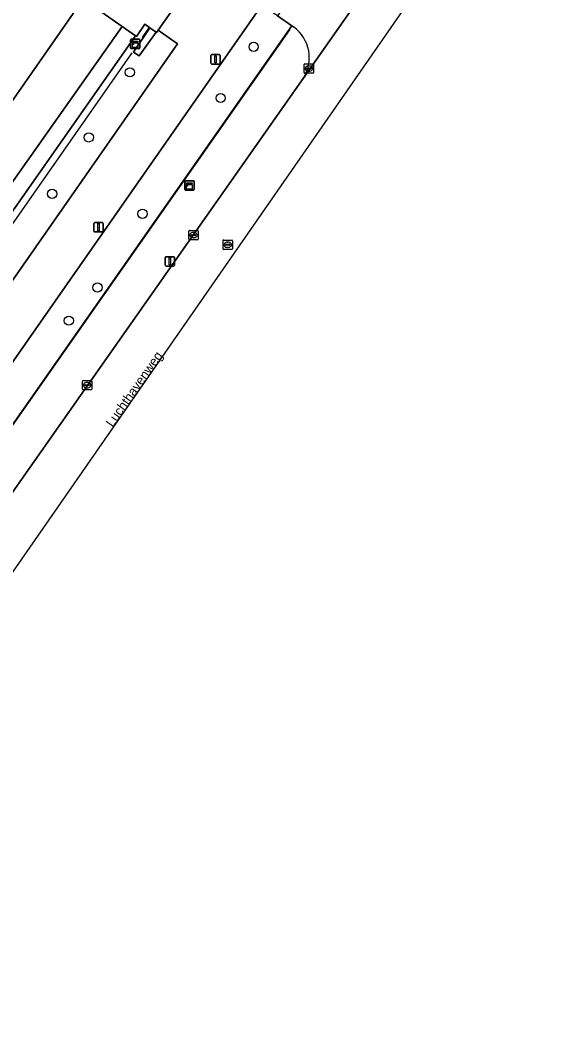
# Model space of a CAD drawing. Extents: x 152881 to 155736, y 382924 to 386919.
# Drawn here: x 155124.1 to 155179.5, y 385020.9 to 385127.6 of the extents above; entities that cross this region are included whole.
import ezdxf

# ---------------------------------------------------------------- set-up
doc = ezdxf.new("R2010")
doc.units = 0
for name, color, linetype in [('IMGEO_Berm_groen', 7, 'Continuous'), ('IMGEO_Boom', 7, 'Continuous'), ('IMGEO_Groenvoorziening', 7, 'Continuous'), ('IMGEO_Hek', 7, 'Continuous'), ('IMGEO_Kast', 7, 'Continuous'), ('IMGEO_Kolk', 7, 'Continuous'), ('IMGEO_Lichtmast', 7, 'Continuous'), ('IMGEO_Openbare_ruimte_label', 7, 'Continuous'), ('IMGEO_Parkeervlak_gesloten', 7, 'Continuous'), ('IMGEO_Rijbaan_lokaal_gesloten', 7, 'Continuous'), ('IMGEO_Rijbaan_lokaal_open', 7, 'Continuous'), ('IMGEO_Rioolput', 7, 'Continuous'), ('IMGEO_Voetpad_gesloten', 7, 'Continuous'), ('IMGEO_Voetpad_halfverhard', 7, 'Continuous'), ('IMGEO_Voetpad_open', 7, 'Continuous')]:
    doc.layers.add(name, color=color, linetype=linetype)

msp = doc.modelspace()

# ---------------------------------------------------------------- linework, layer by layer
at = {"layer": 'IMGEO_Berm_groen'}
for points in [[(155153.15, 385126.84), (155152.98, 385126.96), (155077.88, 385019.79)], [(155083.99, 385021.59), (155085.72, 385024.04), (155090.04, 385030.16), (155094.27, 385036.18), (155154.18, 385121.35)]]:
    msp.add_lwpolyline(points, dxfattribs=at)
msp.add_arc((155150.81, 385123.56), 4.03, 326.832, 54.5812, dxfattribs=at)
at = {"layer": 'IMGEO_Boom'}
for centre in [(155148.93, 385124.73), (155135.77, 385122.02), (155145.41, 385119.29), (155131.4, 385115.11), (155127.51, 385109.12), (155137.11, 385107), (155132.33, 385099.17), (155129.28, 385095.65)]:
    msp.add_circle(centre, 0.489, dxfattribs=at)
at = {"layer": 'IMGEO_Groenvoorziening'}
for points in [[(155152.98, 385126.96), (155151.45, 385128.02), (155149.8, 385129.16), (155122.1, 385089.51), (155100.75, 385059.03), (155084.65, 385036.05), (155074.44, 385021.51), (155076.09, 385020.39)], [(155077.88, 385019.79), (155152.98, 385126.96)]]:
    msp.add_lwpolyline(points, dxfattribs=at)
msp.add_lwpolyline([(155138.78, 385126.49), (155138.61, 385126.25), (155138.55, 385126.3), (155136.76, 385123.79), (155136.17, 385124.18), (155137.88, 385126.76), (155137.37, 385127.12), (155136.46, 385125.83), (155136.36, 385125.89), (155115.83, 385096.65), (155114.29, 385097.69), (155092.42, 385066.08), (155097.23, 385062.74), (155119.33, 385094.28), (155140.82, 385125.04)], close=True, dxfattribs=at)
at = {"layer": 'IMGEO_Hek'}
for points in [[(155152.72, 385126.53), (155081.57, 385025.07)], [(155137.75, 385126.72), (155137.06, 385125.72)], [(155094.55, 385064.82), (155136, 385124.09)]]:
    msp.add_lwpolyline(points, dxfattribs=at)
at = {"layer": 'IMGEO_Kast'}
for p, q in [((155135.83, 385124.61), (155135.83, 385125.45)), ((155135.83, 385125.45), (155135.83, 385124.61)), ((155135.91, 385125.54), (155136.75, 385125.54)), ((155136.75, 385125.54), (155135.91, 385125.54)), ((155136.83, 385125.46), (155136.83, 385124.62)), ((155136.83, 385124.62), (155136.83, 385125.46)), ((155136.76, 385124.54), (155135.92, 385124.54)), ((155135.92, 385124.54), (155136.76, 385124.54)), ((155141.6, 385109.58), (155141.6, 385110.42)), ((155141.6, 385110.42), (155141.6, 385109.58)), ((155141.67, 385110.51), (155142.51, 385110.51)), ((155142.51, 385110.51), (155141.67, 385110.51)), ((155142.6, 385110.43), (155142.6, 385109.59)), ((155142.6, 385109.59), (155142.6, 385110.43)), ((155142.52, 385109.51), (155141.68, 385109.51)), ((155141.68, 385109.51), (155142.52, 385109.51))]:
    msp.add_line(p, q, dxfattribs=at)
for points in [[(155136.03, 385125.33), (155136.63, 385125.33), (155136.63, 385125.24), (155136.03, 385125.24), (155136.03, 385125.33)], [(155136.03, 385125.15), (155136.63, 385125.15), (155136.63, 385124.66), (155136.03, 385124.66), (155136.03, 385125.15)], [(155141.79, 385110.3), (155142.39, 385110.3), (155142.39, 385110.21), (155141.79, 385110.21), (155141.79, 385110.3)], [(155141.79, 385110.12), (155142.39, 385110.12), (155142.39, 385109.63), (155141.79, 385109.63), (155141.79, 385110.12)]]:
    msp.add_lwpolyline(points, dxfattribs=at)
for centre in [(155136.11, 385125), (155141.88, 385109.97)]:
    msp.add_circle(centre, 0.0377, dxfattribs=at)
for centre, start, end in [((155135.91, 385125.46), 92.4484, 184.2845), ((155135.91, 385125.46), 92.4484, 184.2845), ((155135.91, 385124.62), 182.4484, 274.2845), ((155135.91, 385124.62), 182.4484, 274.2845), ((155136.75, 385125.46), 2.4484, 94.2845), ((155136.75, 385125.46), 2.4484, 94.2845), ((155136.75, 385124.62), 272.4484, 4.2845), ((155136.75, 385124.62), 272.4484, 4.2845), ((155141.68, 385110.43), 92.4484, 184.2845), ((155141.68, 385110.43), 92.4484, 184.2845), ((155142.52, 385110.43), 2.4484, 94.2845), ((155142.52, 385110.43), 2.4484, 94.2845), ((155141.68, 385109.59), 182.4484, 274.2845), ((155141.68, 385109.59), 182.4484, 274.2845), ((155142.52, 385109.59), 272.4484, 4.2845), ((155142.52, 385109.59), 272.4484, 4.2845)]:
    msp.add_arc(centre, 0.0779, start, end, dxfattribs=at)
at = {"layer": 'IMGEO_Kolk'}
for p, q in [((155154.28, 385121.99), (155154.28, 385122.84)), ((155154.36, 385122.92), (155155.21, 385122.92)), ((155154.77, 385122.7), (155154.8, 385122.7)), ((155155.28, 385122.84), (155155.28, 385121.99)), ((155155.21, 385121.92), (155154.36, 385121.92)), ((155154.54, 385122.41), (155154.54, 385122.42)), ((155154.98, 385122.37), (155154.58, 385122.37)), ((155154.59, 385122.46), (155154.98, 385122.46)), ((155154.79, 385122.14), (155154.77, 385122.14)), ((155155.03, 385122.42), (155155.03, 385122.41)), ((155142.04, 385104.31), (155142.04, 385105.17)), ((155142.11, 385105.24), (155142.96, 385105.24)), ((155142.29, 385104.73), (155142.29, 385104.75)), ((155142.73, 385104.7), (155142.33, 385104.7)), ((155142.34, 385104.78), (155142.74, 385104.78)), ((155142.52, 385105.02), (155142.55, 385105.02)), ((155142.55, 385104.46), (155142.52, 385104.46)), ((155142.78, 385104.75), (155142.78, 385104.73)), ((155143.04, 385105.17), (155143.04, 385104.31)), ((155142.96, 385104.24), (155142.11, 385104.24)), ((155130.72, 385088.37), (155130.72, 385089.23)), ((155130.79, 385089.3), (155131.65, 385089.3)), ((155130.98, 385088.79), (155130.98, 385088.81)), ((155131.02, 385088.84), (155131.42, 385088.84)), ((155131.42, 385088.76), (155131.02, 385088.76)), ((155131.21, 385089.08), (155131.23, 385089.08)), ((155131.23, 385088.52), (155131.21, 385088.52)), ((155131.46, 385088.81), (155131.46, 385088.79)), ((155131.72, 385089.23), (155131.72, 385088.37)), ((155131.65, 385088.3), (155130.79, 385088.3))]:
    msp.add_line(p, q, dxfattribs=at)
for points in [[(155154.28, 385121.99), (155154.28, 385122.84)], [(155154.36, 385122.92), (155155.21, 385122.92)], [(155155.28, 385122.84), (155155.28, 385121.99)], [(155155.21, 385121.92), (155154.36, 385121.92)], [(155142.04, 385104.31), (155142.04, 385105.17)], [(155142.11, 385105.24), (155142.96, 385105.24)], [(155143.04, 385105.17), (155143.04, 385104.31)], [(155142.96, 385104.24), (155142.11, 385104.24)], [(155130.72, 385088.37), (155130.72, 385089.23)], [(155130.79, 385089.3), (155131.65, 385089.3)], [(155131.72, 385089.23), (155131.72, 385088.37)], [(155131.65, 385088.3), (155130.79, 385088.3)]]:
    msp.add_lwpolyline(points, dxfattribs=at)
for centre, radius, start, end in [((155154.36, 385122.84), 0.0765, 91.552, 178.448), ((155154.36, 385122.84), 0.0765, 91.552, 178.448), ((155155.21, 385122.84), 0.0765, 1.552, 88.448), ((155155.21, 385122.84), 0.0765, 1.552, 88.448), ((155154.36, 385121.99), 0.0765, 181.552, 268.448), ((155154.36, 385121.99), 0.0765, 181.552, 268.448), ((155154.58, 385122.42), 0.0403, 85.8775, 175.7526), ((155154.58, 385122.41), 0.0366, 178.938, 274.7102), ((155154.99, 385122.42), 0.0386, 1.7309, 96.639), ((155154.98, 385122.42), 0.043, 264.8664, 352.4533), ((155155.21, 385121.99), 0.0765, 271.552, 358.448), ((155155.21, 385121.99), 0.0765, 271.552, 358.448), ((155142.11, 385105.16), 0.0765, 91.552, 178.448), ((155142.11, 385105.16), 0.0765, 91.552, 178.448), ((155142.34, 385104.74), 0.0403, 85.8775, 175.7526), ((155142.33, 385104.73), 0.0366, 178.938, 274.7102), ((155142.74, 385104.74), 0.043, 264.8664, 352.4533), ((155142.74, 385104.74), 0.0386, 1.7309, 96.639), ((155142.96, 385105.16), 0.0765, 1.552, 88.448), ((155142.96, 385105.16), 0.0765, 1.552, 88.448), ((155142.11, 385104.31), 0.0765, 181.552, 268.448), ((155142.11, 385104.31), 0.0765, 181.552, 268.448), ((155142.96, 385104.31), 0.0765, 271.552, 358.448), ((155142.96, 385104.31), 0.0765, 271.552, 358.448), ((155130.8, 385089.22), 0.0765, 91.552, 178.448), ((155130.8, 385089.22), 0.0765, 91.552, 178.448), ((155130.8, 385088.38), 0.0765, 181.552, 268.448), ((155130.8, 385088.38), 0.0765, 181.552, 268.448), ((155131.02, 385088.8), 0.0403, 85.8775, 175.7526), ((155131.02, 385088.79), 0.0366, 178.938, 274.7102), ((155131.42, 385088.8), 0.0386, 1.7309, 96.639), ((155131.42, 385088.8), 0.043, 264.8664, 352.4533), ((155131.64, 385089.22), 0.0765, 1.552, 88.448), ((155131.64, 385089.22), 0.0765, 1.552, 88.448), ((155131.64, 385088.38), 0.0765, 271.552, 358.448), ((155131.64, 385088.38), 0.0765, 271.552, 358.448)]:
    msp.add_arc(centre, radius, start, end, dxfattribs=at)
for centre, major_axis, ratio, start_param, end_param in [((155154.77, 385122.42), (-0.387, 0.002), 0.722429, 4.712389, 7.853982), ((155154.79, 385122.42), (-0.39, 0.002), 0.717154, 1.570796, 4.712389), ((155142.52, 385104.74), (-0.387, 0.002), 0.722429, 4.712389, 7.853982), ((155142.55, 385104.74), (-0.39, 0.002), 0.717154, 1.570796, 4.712389), ((155131.21, 385088.8), (-0.387, 0.002), 0.722429, 4.712389, 7.853982), ((155131.23, 385088.8), (-0.39, 0.002), 0.717154, 1.570796, 4.712389)]:
    msp.add_ellipse(centre, major_axis=major_axis, ratio=ratio, start_param=start_param, end_param=end_param, dxfattribs=at)
at = {"layer": 'IMGEO_Lichtmast'}
for p, q in [((155144.37, 385123), (155144.37, 385123.8)), ((155144.37, 385123.8), (155144.37, 385123)), ((155144.47, 385123.9), (155145.26, 385123.9)), ((155145.26, 385123.9), (155144.47, 385123.9)), ((155145.36, 385123.8), (155145.36, 385123)), ((155145.36, 385123), (155145.36, 385123.8)), ((155145.26, 385122.9), (155144.47, 385122.9)), ((155144.47, 385122.9), (155145.26, 385122.9)), ((155131.93, 385105.17), (155131.93, 385105.97)), ((155131.93, 385105.97), (155131.93, 385105.17)), ((155132.03, 385106.07), (155132.82, 385106.07)), ((155132.82, 385106.07), (155132.03, 385106.07)), ((155132.92, 385105.97), (155132.92, 385105.17)), ((155132.92, 385105.17), (155132.92, 385105.97)), ((155132.82, 385105.07), (155132.03, 385105.07)), ((155132.03, 385105.07), (155132.82, 385105.07)), ((155139.51, 385101.54), (155139.51, 385102.34)), ((155139.51, 385102.34), (155139.51, 385101.54)), ((155139.61, 385102.44), (155140.4, 385102.44)), ((155140.4, 385102.44), (155139.61, 385102.44)), ((155140.5, 385102.34), (155140.5, 385101.54)), ((155140.5, 385101.54), (155140.5, 385102.34)), ((155140.4, 385101.44), (155139.61, 385101.44)), ((155139.61, 385101.44), (155140.4, 385101.44))]:
    msp.add_line(p, q, dxfattribs=at)
for points in [[(155144.79, 385123.78), (155144.94, 385123.78), (155144.94, 385123.03), (155144.79, 385123.03), (155144.79, 385123.78)], [(155132.35, 385105.95), (155132.5, 385105.95), (155132.5, 385105.2), (155132.35, 385105.2), (155132.35, 385105.95)], [(155139.93, 385102.32), (155140.08, 385102.32), (155140.08, 385101.57), (155139.93, 385101.57), (155139.93, 385102.32)]]:
    msp.add_lwpolyline(points, dxfattribs=at)
for centre, start, end in [((155144.47, 385123.8), 90, 180), ((155144.47, 385123.8), 90, 180), ((155145.26, 385123.8), 0, 90), ((155145.26, 385123.8), 360, 90), ((155144.47, 385123), 180, 270), ((155144.47, 385123), 180, 270), ((155145.26, 385123), 270, 0), ((155145.26, 385123), 270, 0), ((155132.03, 385105.97), 90, 180), ((155132.03, 385105.97), 90, 180), ((155132.82, 385105.97), 0, 90), ((155132.82, 385105.97), 360, 90), ((155132.03, 385105.17), 180, 270), ((155132.03, 385105.17), 180, 270), ((155132.82, 385105.17), 270, 0), ((155132.82, 385105.17), 270, 0), ((155139.61, 385102.34), 90, 180), ((155139.61, 385102.34), 90, 180), ((155140.4, 385102.34), 0, 90), ((155140.4, 385102.34), 360, 90), ((155139.61, 385101.54), 180, 270), ((155139.61, 385101.54), 180, 270), ((155140.4, 385101.54), 270, 0), ((155140.4, 385101.54), 270, 0)]:
    msp.add_arc(centre, 0.1, start, end, dxfattribs=at)
at = {"layer": 'IMGEO_Parkeervlak_gesloten'}
msp.add_lwpolyline([(155114.29, 385097.69), (155134.95, 385126.88), (155130.79, 385129.81), (155069.62, 385042.09), (155073.78, 385039.15), (155090.72, 385063.63), (155091.08, 385064.15), (155092.42, 385066.08)], close=True, dxfattribs=at)
at = {"layer": 'IMGEO_Rijbaan_lokaal_gesloten'}
msp.add_lwpolyline([(155135.47, 385257.39), (155071.74, 385167.61), (155005.79, 385074.76), (154999.5, 385079.35), (154997.65, 385076.81), (155004.93, 385071.82), (155007.93, 385076.03), (155069.81, 385033.42), (155073.78, 385039.15), (155069.62, 385042.09), (155130.79, 385129.81), (155124.35, 385134.34), (155129.88, 385142.17), (155133.96, 385147.99)], dxfattribs=at)
msp.add_lwpolyline([(155098.46, 385033.23), (155193.44, 385169.83), (155191.47, 385171.19), (155189.88, 385172.28), (155162.69, 385133.52), (155154.18, 385121.35), (155094.27, 385036.18)], close=True, dxfattribs=at)
at = {"layer": 'IMGEO_Rijbaan_lokaal_open'}
for points in [[(155157.03, 385132.71), (155155.52, 385133.76), (155151.45, 385128.02), (155152.98, 385126.96), (155153.15, 385126.84)], [(155154.18, 385121.35), (155162.69, 385133.52)]]:
    msp.add_lwpolyline(points, dxfattribs=at)
msp.add_arc((155150.81, 385123.56), 4.03, 326.832, 54.5812, dxfattribs=at)
at = {"layer": 'IMGEO_Rioolput'}
for p, q in [((155145.67, 385103.29), (155145.67, 385104.14)), ((155145.74, 385104.21), (155146.59, 385104.21)), ((155145.93, 385103.71), (155145.93, 385103.72)), ((155145.97, 385103.76), (155146.37, 385103.76)), ((155146.36, 385103.67), (155145.97, 385103.67)), ((155146.18, 385103.43), (155146.15, 385103.43)), ((155146.16, 385103.99), (155146.18, 385103.99)), ((155146.41, 385103.72), (155146.41, 385103.71)), ((155146.67, 385104.14), (155146.67, 385103.29)), ((155146.59, 385103.21), (155145.74, 385103.21))]:
    msp.add_line(p, q, dxfattribs=at)
for points in [[(155145.67, 385103.29), (155145.67, 385104.14)], [(155145.74, 385104.21), (155146.59, 385104.21)], [(155146.67, 385104.14), (155146.67, 385103.29)], [(155146.59, 385103.21), (155145.74, 385103.21)]]:
    msp.add_lwpolyline(points, dxfattribs=at)
for centre, radius, start, end in [((155145.74, 385104.14), 0.0765, 91.552, 178.448), ((155145.74, 385104.14), 0.0765, 91.552, 178.448), ((155145.74, 385103.29), 0.0765, 181.552, 268.448), ((155145.74, 385103.29), 0.0765, 181.552, 268.448), ((155145.97, 385103.72), 0.0403, 85.8775, 175.7526), ((155145.96, 385103.71), 0.0366, 178.938, 274.7102), ((155146.37, 385103.71), 0.043, 264.8664, 352.4533), ((155146.37, 385103.72), 0.0386, 1.7309, 96.639), ((155146.59, 385104.14), 0.0765, 1.552, 88.448), ((155146.59, 385104.14), 0.0765, 1.552, 88.448), ((155146.59, 385103.29), 0.0765, 271.552, 358.448), ((155146.59, 385103.29), 0.0765, 271.552, 358.448)]:
    msp.add_arc(centre, radius, start, end, dxfattribs=at)
for centre, major_axis, ratio, start_param, end_param in [((155146.15, 385103.71), (-0.387, 0.002), 0.722429, 4.712389, 7.853982), ((155146.18, 385103.71), (-0.39, 0.002), 0.717154, 1.570796, 4.712389)]:
    msp.add_ellipse(centre, major_axis=major_axis, ratio=ratio, start_param=start_param, end_param=end_param, dxfattribs=at)
at = {"layer": 'IMGEO_Voetpad_gesloten'}
for points in [[(155142.38, 385134.28), (155141.96, 385133.68), (155140.65, 385131.8), (155141.88, 385130.95), (155138.78, 385126.49), (155140.82, 385125.04), (155119.33, 385094.28), (155097.23, 385062.74), (155092.42, 385066.08), (155091.08, 385064.15), (155090.72, 385063.63), (155095.5, 385060.27), (155080.57, 385038.96), (155079.75, 385039.54), (155072.86, 385029.71), (155071.21, 385030.85), (155067.78, 385025.95), (155074.31, 385021.33), (155074.44, 385021.51), (155084.65, 385036.05), (155100.75, 385059.03), (155122.1, 385089.51), (155149.8, 385129.16)], [(155136.36, 385125.89), (155134.95, 385126.88), (155114.29, 385097.69), (155115.83, 385096.65)]]:
    msp.add_lwpolyline(points, close=True, dxfattribs=at)
at = {"layer": 'IMGEO_Voetpad_halfverhard'}
msp.add_lwpolyline([(155138.55, 385126.3), (155137.88, 385126.76), (155136.17, 385124.18), (155136.76, 385123.79)], close=True, dxfattribs=at)
at = {"layer": 'IMGEO_Voetpad_open'}
msp.add_lwpolyline([(155129.88, 385142.17), (155124.35, 385134.34), (155130.79, 385129.81), (155134.95, 385126.88), (155136.36, 385125.89), (155136.46, 385125.83), (155137.37, 385127.12), (155137.88, 385126.76), (155138.55, 385126.3), (155138.61, 385126.25), (155138.78, 385126.49), (155141.88, 385130.95), (155140.65, 385131.8), (155141.96, 385133.68), (155141.8, 385133.79)], dxfattribs=at)

# ---------------------------------------------------------------- texts
at = {"layer": 'IMGEO_Openbare_ruimte_label'}
msp.add_text('Luchthavenweg', height=1, rotation=55.0549, dxfattribs=at).set_placement((155133.94, 385084.26))

doc.saveas('drawing.dxf')
